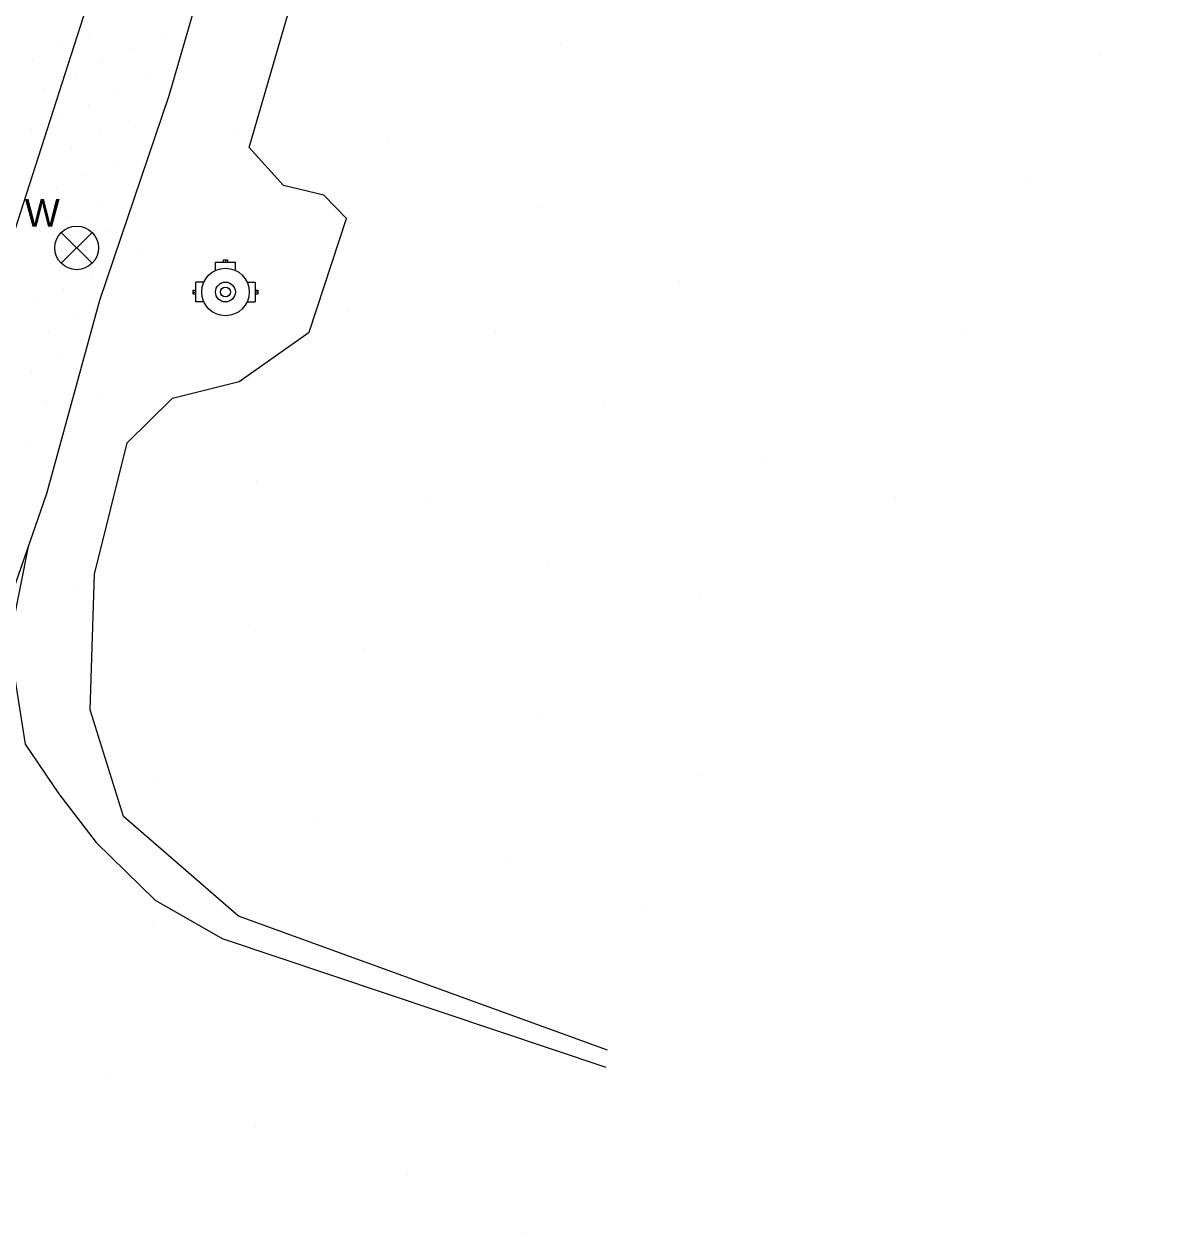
# Model space of a CAD drawing. Extents: x 0 to 1739264, y 0 to 465304.
# Drawn here: x 1738691.3 to 1738763.7, y 464086.3 to 464162.5 of the extents above; entities that cross this region are included whole.
import ezdxf

# ---------------------------------------------------------------- set-up
doc = ezdxf.new("R2010")
doc.units = 0
for name, color, linetype in [('Default', 7, 'Continuous'), ('S_Ground_SpotElevation', 7, 'Continuous'), ('S_Terrain_High_Points', 7, 'Continuous'), ('S_Terrain_Holes', 7, 'Continuous'), ('S_Terrain_Imported_Contours', 7, 'Continuous'), ('S_Terrain_Voids', 7, 'Continuous'), ('S_Utilities_Hydrant', 7, 'Continuous'), ('S_Utilities_UG_Water_Gate', 7, 'Continuous')]:
    doc.layers.add(name, color=color, linetype=linetype)

# ---------------------------------------------------------------- blocks, each defined once
blk = doc.blocks.new('POINT_DISPLAY')
at = {"layer": 'Default'}
blk.add_line((0, 0), (0, 0), dxfattribs=at)

msp = doc.modelspace()

# ---------------------------------------------------------------- linework, layer by layer
at = {"layer": 'S_Terrain_High_Points'}
msp.add_lwpolyline([(1738691.571349, 464129.570427), (1738690.5471, 464124.496004), (1738690.7142, 464121.261507), (1738691.3672, 464117.125703), (1738693.4911, 464113.989595), (1738695.8482, 464110.92209), (1738699.5591, 464107.304597), (1738703.7884, 464104.889802), (1738727.9554, 464096.773805)], dxfattribs=at)
at = {"layer": 'S_Terrain_Holes'}
msp.add_lwpolyline([(1738651.189199, 464006.679201), (1738660.596601, 464036.365297), (1738671.612301, 464070.082094), (1738677.8174, 464088.4769), (1738683.0778, 464104.503694), (1738687.3633, 464117.484498), (1738692.7376, 464132.920015), (1738696.0879, 464145.086107), (1738700.4382, 464157.984804), (1738705.4912, 464175.369295), (1738712.3665, 464196.482698), (1738719.617201, 464217.112092), (1738728.162701, 464246.886598)], dxfattribs=at)
at = {"layer": 'S_Terrain_Imported_Contours'}
msp.add_lwpolyline([(1738644.745199, 464009.062105), (1738654.8025, 464040.277803), (1738669.121099, 464084.176698), (1738689.2048, 464144.832002), (1738706.63, 464198.951005), (1738722.465099, 464248.7679), (1738739.417002, 464302.301599), (1738750.081598, 464335.5645), (1738762.818899, 464375.208381), (1738775.1704, 464413.370124), (1738788.2376, 464452.934486), (1738800.295598, 464489.747413), (1738816.4241, 464539.282294), (1738816.833754, 464540.526168)], dxfattribs=at)
at = {"layer": 'S_Terrain_Voids'}
msp.add_lwpolyline([(1738728.0646, 464097.846315), (1738704.808, 464106.292909), (1738697.5788, 464112.576814), (1738695.4714, 464119.286592), (1738695.7428, 464127.825899), (1738697.8056, 464136.104707), (1738700.6637, 464138.907793), (1738704.8537, 464139.969194), (1738709.2592, 464143.068498), (1738711.6223, 464150.231706), (1738710.1859, 464151.699998), (1738707.644, 464152.301698), (1738705.4919, 464154.696504), (1738712.3504, 464178.309404), (1738720.401501, 464201.174592), (1738726.1929, 464213.578493), (1738732.557001, 464222.761507), (1738732.945501, 464226.492692), (1738732.971102, 464235.283006), (1738732.942598, 464244.125001), (1738760.736898, 464334.173501)], dxfattribs=at)
at = {"layer": 'S_Utilities_Hydrant'}
for p, q in [((1738703.368231, 464146.961103), (1738703.368231, 464147.471507)), ((1738703.368231, 464147.471507), (1738704.615769, 464147.471507)), ((1738703.992, 464147.637845), (1738703.992, 464147.471507)), ((1738704.615769, 464146.961103), (1738704.615769, 464147.471507)), ((1738701.954355, 464145.6002), (1738702.120693, 464145.6002)), ((1738702.631097, 464146.223969), (1738702.120693, 464146.223969)), ((1738702.120693, 464144.976431), (1738702.120693, 464146.223969)), ((1738705.352903, 464146.223969), (1738705.863307, 464146.223969)), ((1738705.863307, 464146.223969), (1738705.863307, 464144.976431)), ((1738706.029645, 464145.6002), (1738705.863307, 464145.6002)), ((1738702.631097, 464144.976431), (1738702.120693, 464144.976431)), ((1738705.352903, 464144.976431), (1738705.863307, 464144.976431))]:
    msp.add_line(p, q, dxfattribs=at)
for points in [[(1738703.867246, 464147.471507), (1738703.867246, 464147.637845), (1738704.116754, 464147.637845), (1738704.116754, 464147.471507)], [(1738702.120693, 464145.475446), (1738701.954355, 464145.475446), (1738701.954355, 464145.724954), (1738702.120693, 464145.724954)], [(1738705.863307, 464145.724954), (1738706.029645, 464145.724954), (1738706.029645, 464145.475446), (1738705.863307, 464145.475446)]]:
    msp.add_lwpolyline(points, dxfattribs=at)
for radius in [1.497045, 0.623769, 0.311884]:
    msp.add_circle((1738703.992, 464145.6002), radius, dxfattribs=at)
at = {"layer": 'S_Utilities_UG_Water_Gate'}
for p, q in [((1738693.649643, 464149.348757), (1738695.590357, 464147.408043)), ((1738693.649643, 464147.408043), (1738695.590357, 464149.348757))]:
    msp.add_line(p, q, dxfattribs=at)
msp.add_circle((1738694.62, 464148.3784), 1.372292, dxfattribs=at)

# ---------------------------------------------------------------- block references
at = {"layer": 'S_Ground_SpotElevation'}
for p in [(1738695.444099, 464161.819908), (1738700.112701, 464161.6791), (1738693.6034, 464161.070305), (1738698.179801, 464160.851707), (1738725.079697, 464161.248638), (1738691.848102, 464160.197105), (1738759.052293, 464160.501568), (1738696.2569, 464160.000709), (1738694.618301, 464159.276909), (1738699.1076, 464159.043907), (1738692.567401, 464158.394707), (1738697.1646, 464158.152504), (1738695.355701, 464157.413612), (1738693.441501, 464156.550011), (1738697.900199, 464156.320305), (1738691.780501, 464155.7976), (1738696.048801, 464155.567711), (1738704.762803, 464155.742046), (1738694.312499, 464154.728401), (1738714.169694, 464155.084087), (1738692.433398, 464153.957909), (1738697.0102, 464153.782112), (1738695.165599, 464152.928612), (1738754.366196, 464152.524761), (1738693.329101, 464152.136207), (1738691.5577, 464151.362404), (1738695.947398, 464151.11541), (1738723.730485, 464151.00816), (1738694.153201, 464150.278099), (1738692.250201, 464149.458107), (1738696.501102, 464149.448707), (1738694.932101, 464148.52961), (1738698.710191, 464148.093365), (1738693.083701, 464147.620506), (1738695.542602, 464146.721809), (1738693.8143, 464145.808601), (1738732.5645, 464146.201153), (1738692.145301, 464145.057106), (1738711.707413, 464144.356548), (1738694.644099, 464143.986214), (1738692.821502, 464143.141106), (1738720.984513, 464143.025616), (1738750.554398, 464142.939556), (1738693.745601, 464141.386299), (1738691.804, 464140.525505), (1738692.727801, 464138.787605), (1738696.162309, 464139.107403), (1738727.898698, 464138.611675), (1738691.6869, 464136.087295), (1738737.982896, 464134.984478), (1738705.938493, 464133.709576), (1738716.857804, 464132.546246), (1738746.212998, 464132.605938), (1738724.274888, 464128.401104), (1738694.4572, 464126.858135), (1738733.936204, 464126.538311), (1738705.424485, 464124.60545), (1738712.71431, 464123.142315), (1738723.700486, 464118.995953), (1738733.810807, 464115.126446), (1738699.520798, 464114.764752), (1738709.588914, 464112.246563), (1738721.676896, 464109.802593), (1738730.311906, 464106.964825), (1738699.448502, 464105.686871), (1738696.459, 464096.363262), (1738705.854386, 464093.121075), (1738715.467393, 464090.115948), (1738722.72429, 464086.301739)]:
    msp.add_blockref('POINT_DISPLAY', p, dxfattribs=at)

# ---------------------------------------------------------------- texts
at = {"layer": 'S_Utilities_UG_Water_Gate'}
msp.add_text('W', height=1.746553, dxfattribs=at).set_placement((1738691.351222, 464149.71048))

doc.saveas('drawing.dxf')
